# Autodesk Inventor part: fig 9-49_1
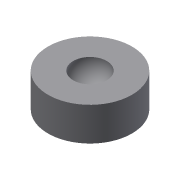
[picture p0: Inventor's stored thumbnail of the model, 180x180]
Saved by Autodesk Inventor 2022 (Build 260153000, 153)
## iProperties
Created: 2013-03
Part Number: fig 9-49_1
Material: Generic
Document SubType Name: Modeling
Designer: CADCIM
Density: 1 g/cm^3
Appearance: Default
Author: CADCIM
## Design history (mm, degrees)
sketch "Sketch1"
  geometry: C1 r 12.5 at (0, 0); 1 further point
  constraints: 1 centre point, 1 coincident
  dimensions: "d0" = 25 diameter of C1
extrude "Extrusion1" new body sketch "Sketch1" distance "d2" = 10; taper "d3" = 0 deg
sketch "Sketch2"
  geometry: L1 (12.5, 10)-(-12.5, 10) reference; L2 (-5, 10)-(5, 10); A1 r 5 centre (0, 10) between (-5, 10) and (5, 10); 1 further point
  constraints: 2 end point, 2 point on circle, 2 point on line, 1 centre point, 1 midpoint
  dimensions: "d4" = 10 diameter of A1
revolve "Revolution1" sketch "Sketch2" stored, may be unused: angle "d6" = 90 deg
body "Solid1"
